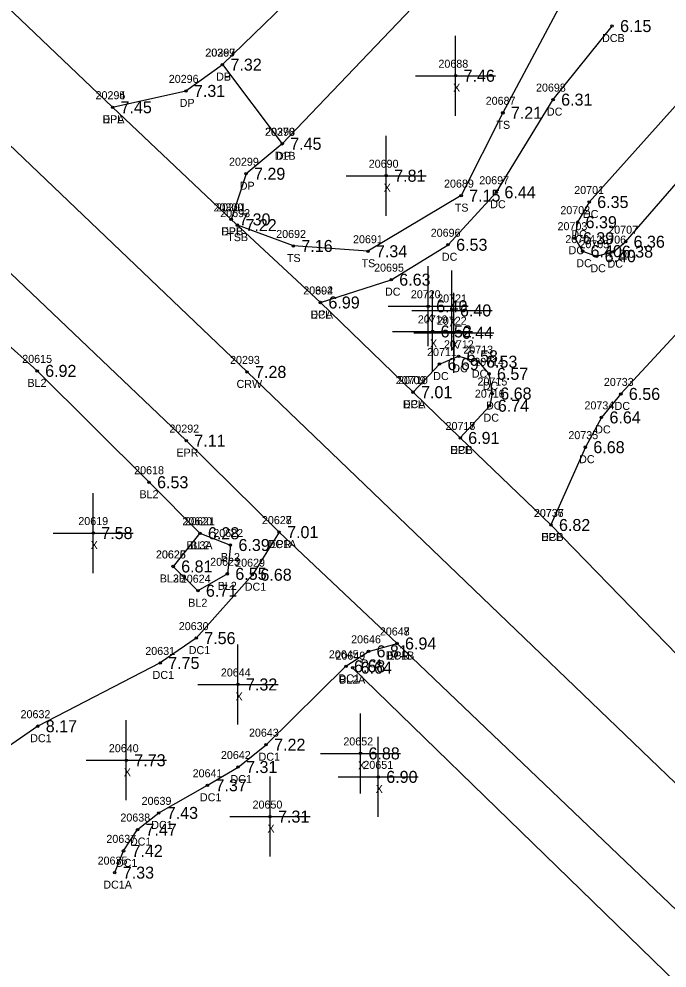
# Model space of a CAD drawing. Extents: x 2608745 to 2610333, y 641917 to 643463.
# Drawn here: x 2609150.7 to 2609231.6, y 642947.8 to 643066.4 of the extents above; entities that cross this region are included whole.
import ezdxf

# ---------------------------------------------------------------- set-up
doc = ezdxf.new("R2010")
doc.units = 0
for name, color, linetype in [('RD_DTM_BkLn1', 7, 'Continuous'), ('RD_DTM_BkLn2', 7, 'Continuous'), ('RD_DTM_BkLn_txCode', 7, 'Continuous'), ('RD_EX_Conc', 7, 'Continuous'), ('RD_EX_Conc_txCode', 7, 'Continuous'), ('RD_EX_Driveway', 7, 'Continuous'), ('RD_EX_Driveway_txCode', 7, 'Continuous'), ('RD_EX_Misc', 7, 'Continuous'), ('RD_EX_Misc_txCode', 7, 'Continuous'), ('RD_EX_Road', 7, 'Continuous'), ('RD_EX_Road_txCode', 7, 'Continuous'), ('RD_EX_TX_Conc_ELEV', 7, 'Continuous'), ('RD_EX_TX_Driveway_ELEV', 7, 'Continuous'), ('RD_EX_TX_Misc_ELEV', 7, 'Continuous'), ('RD_EX_TX_Road_ELEV', 7, 'Continuous'), ('RD_HC_Survey_ELEV', 7, 'Continuous'), ('RD_HC_Survey_txCode', 7, 'Continuous'), ('RD_SMD_Locator', 7, 'Continuous')]:
    doc.layers.add(name, color=color, linetype=linetype)

msp = doc.modelspace()

# ---------------------------------------------------------------- linework, layer by layer
at = {"layer": 'RD_DTM_BkLn1'}
msp.add_line((2609173.31, 643002.14), (2609169.97, 642997.99), dxfattribs=at)
for points in [[(2608814.73, 643373.65), (2608890.45, 643300.26), (2608962.19, 643231.31), (2609034.91, 643161.19), (2609108.48, 643089.9), (2609179.19, 643022.29), (2609255.71, 642948.78), (2609335.19, 642871.73), (2609410.7, 642798.48), (2609491.67, 642719.95), (2609518.07, 642695.15)], [(2609126.24, 643046.39), (2609152.99, 643022.42), (2609166.96, 643008.51), (2609173.31, 643002.14), (2609177.12, 643000.67), (2609176.73, 642997.07), (2609173.06, 642994.96), (2609169.97, 642997.99)], [(2609192.37, 642985.35), (2609243.37, 642935.72), (2609261.87, 642916.52), (2609260.59, 642912.35), (2609259.28, 642907.38), (2609258.26, 642905.81), (2609261.26, 642892.15), (2609237.69, 642882.51), (2609215.85, 642875.95), (2609203.21, 642875.18)]]:
    msp.add_lwpolyline(points, dxfattribs=at)
at = {"layer": 'RD_DTM_BkLn2'}
msp.add_lwpolyline([(2609237.48, 643094.02), (2609220.03, 643071.4), (2609211.12, 643054.65), (2609205.92, 643044.31), (2609194.28, 643037.36), (2609184.97, 643038.02), (2609177.99, 643040.62)], dxfattribs=at)
at = {"layer": 'RD_EX_Conc'}
for points in [[(2609188.35, 643030.96), (2609197.19, 643033.81), (2609204.29, 643038.17), (2609210.32, 643044.73), (2609217.4, 643056.3), (2609224.76, 643065.49)], [(2609270, 643061.09), (2609272.61, 643058.59), (2609260.56, 643044.7), (2609257.72, 643041.97), (2609255.04, 643040.51), (2609251.59, 643039.85), (2609247.63, 643039.74), (2609244.98, 643039.01), (2609242.03, 643037.04), (2609225.85, 643019.54), (2609223.43, 643016.61), (2609221.42, 643012.89), (2609217.13, 643003.17)], [(2609234.1, 643057.12), (2609221.9, 643043.51), (2609220.45, 643040.99), (2609220.11, 643038.99), (2609221.07, 643037.37), (2609222.83, 643036.74), (2609224.97, 643037.31), (2609226.44, 643038.55), (2609238.84, 643052.81)], [(2609199.91, 643019.76), (2609203.21, 643023.27), (2609205.6, 643024.24), (2609208.03, 643023.57), (2609209.39, 643022.05), (2609209.8, 643019.59), (2609209.49, 643018.07), (2609205.8, 643014.04)], [(2609183.19, 643002.28), (2609179.86, 642996.96), (2609172.85, 642989.04), (2609168.35, 642985.94), (2609153.06, 642978.04), (2609140.29, 642969.22), (2609118.23, 642952.79)], [(2609162.68, 642959.75), (2609163.77, 642962.47), (2609165.52, 642965.13), (2609168.17, 642967.21), (2609174.25, 642970.66), (2609178.07, 642972.94), (2609181.57, 642975.73), (2609191.54, 642985.52), (2609194.35, 642987.39), (2609197.91, 642988.37)]]:
    msp.add_lwpolyline(points, dxfattribs=at)
at = {"layer": 'RD_EX_Driveway'}
for points in [[(2609166.46, 643161.04), (2609160.17, 643148.26), (2609190.36, 643122.83), (2609213.32, 643102.87), (2609223.77, 643094.8), (2609208.75, 643077.17), (2609183.58, 643050.78)], [(2609100.57, 643145.92), (2609122.94, 643140.66), (2609155.04, 643137.1), (2609182.05, 643117.56), (2609202.04, 643097.35), (2609199.5, 643083.36), (2609176.12, 643060.67)], [(2609162.4, 643055.35), (2609171.56, 643057.39), (2609176.12, 643060.67), (2609183.58, 643050.78), (2609179.06, 643047.04), (2609177.21, 643041.34)]]:
    msp.add_lwpolyline(points, dxfattribs=at)
at = {"layer": 'RD_EX_Misc'}
for p, q in [((2609205.22, 643054.28), (2609205.22, 643064.28)), ((2609200.22, 643059.28), (2609210.22, 643059.28)), ((2609196.56, 643041.79), (2609196.56, 643051.79)), ((2609191.56, 643046.79), (2609201.56, 643046.79)), ((2609201.8, 643025.49), (2609201.8, 643035.49)), ((2609204.77, 643024.97), (2609204.77, 643034.97)), ((2609202.35, 643022.35), (2609202.35, 643032.35)), ((2609205, 643022.18), (2609205, 643032.18)), ((2609196.8, 643030.49), (2609206.8, 643030.49)), ((2609199.77, 643029.97), (2609209.77, 643029.97)), ((2609197.35, 643027.35), (2609207.35, 643027.35)), ((2609200, 643027.18), (2609210, 643027.18)), ((2609159.99, 642997.16), (2609159.99, 643007.16)), ((2609154.99, 643002.16), (2609164.99, 643002.16)), ((2609178.06, 642978.25), (2609178.06, 642988.25)), ((2609173.06, 642983.25), (2609183.06, 642983.25)), ((2609193.35, 642969.64), (2609193.35, 642979.64)), ((2609164.12, 642968.79), (2609164.12, 642978.79)), ((2609195.57, 642966.71), (2609195.57, 642976.71)), ((2609188.35, 642974.64), (2609198.35, 642974.64)), ((2609159.12, 642973.79), (2609169.12, 642973.79)), ((2609182.06, 642961.75), (2609182.06, 642971.75)), ((2609190.57, 642971.71), (2609200.57, 642971.71)), ((2609177.06, 642966.75), (2609187.06, 642966.75))]:
    msp.add_line(p, q, dxfattribs=at)
at = {"layer": 'RD_EX_Road'}
for points in [[(2608806.89, 643364.99), (2608810.18, 643361.1), (2608820.75, 643351.25), (2608881.81, 643292.24), (2608917.83, 643257.49), (2608933.21, 643242.71), (2608954.07, 643222.83), (2609026.06, 643154.19), (2609039.6, 643139.96), (2609073.88, 643106.95), (2609100.48, 643081.89), (2609124.19, 643058.87), (2609171.61, 643013.71), (2609183.19, 643002.28), (2609197.91, 642988.37), (2609247.59, 642940.95), (2609328.02, 642863.6), (2609402.61, 642790.3), (2609474.23, 642720.69), (2609483.84, 642711.58), (2609495.78, 642699.92), (2609509.81, 642686.45)], [(2609058.51, 643155.46), (2609096.06, 643119.37), (2609116.51, 643099.11), (2609162.4, 643055.35), (2609177.21, 643041.34), (2609188.35, 643030.96), (2609199.91, 643019.76), (2609205.8, 643014.04), (2609217.13, 643003.17), (2609235.83, 642983.9), (2609237.03, 642983.51), (2609256.8, 642965.04), (2609258.49, 642962.51), (2609263.65, 642957.66), (2609344.71, 642879.89), (2609418.83, 642806.19), (2609500.61, 642728.46), (2609512.38, 642716.82), (2609526.19, 642703.5)]]:
    msp.add_lwpolyline(points, dxfattribs=at)
at = {"layer": 'RD_SMD_Locator'}
for centre in [(2609224.76, 643065.49), (2609176.12, 643060.67), (2609176.12, 643060.67), (2609205.22, 643059.28), (2609171.56, 643057.39), (2609217.4, 643056.3), (2609162.4, 643055.35), (2609162.4, 643055.35), (2609211.12, 643054.65), (2609183.58, 643050.78), (2609183.58, 643050.78), (2609179.06, 643047.04), (2609196.56, 643046.79), (2609205.92, 643044.31), (2609210.32, 643044.73), (2609221.9, 643043.51), (2609177.21, 643041.34), (2609177.21, 643041.34), (2609177.99, 643040.62), (2609220.45, 643040.99), (2609184.97, 643038.02), (2609204.29, 643038.17), (2609220.11, 643038.99), (2609226.44, 643038.55), (2609194.28, 643037.36), (2609221.07, 643037.37), (2609224.97, 643037.31), (2609222.83, 643036.74), (2609197.19, 643033.81), (2609188.35, 643030.96), (2609188.35, 643030.96), (2609201.8, 643030.49), (2609204.77, 643029.97), (2609202.35, 643027.35), (2609205, 643027.18), (2609205.6, 643024.24), (2609203.21, 643023.27), (2609208.03, 643023.57), (2609152.99, 643022.42), (2609179.19, 643022.29), (2609209.39, 643022.05), (2609199.91, 643019.76), (2609199.91, 643019.76), (2609209.8, 643019.59), (2609225.85, 643019.54), (2609209.49, 643018.07), (2609223.43, 643016.61), (2609171.61, 643013.71), (2609205.8, 643014.04), (2609205.8, 643014.04), (2609221.42, 643012.89), (2609166.96, 643008.51), (2609217.13, 643003.17), (2609217.13, 643003.17), (2609159.99, 643002.16), (2609173.31, 643002.14), (2609173.31, 643002.14), (2609183.19, 643002.28), (2609183.19, 643002.28), (2609177.12, 643000.67), (2609169.97, 642997.99), (2609169.97, 642997.99), (2609176.73, 642997.07), (2609179.86, 642996.96), (2609173.06, 642994.96), (2609172.85, 642989.04), (2609197.91, 642988.37), (2609197.91, 642988.37), (2609194.35, 642987.39), (2609168.35, 642985.94), (2609191.54, 642985.52), (2609192.37, 642985.35), (2609178.06, 642983.25), (2609153.06, 642978.04), (2609181.57, 642975.73), (2609193.35, 642974.64), (2609164.12, 642973.79), (2609178.07, 642972.94), (2609195.57, 642971.71), (2609174.25, 642970.66), (2609168.17, 642967.21), (2609182.06, 642966.75), (2609165.52, 642965.13), (2609163.77, 642962.47), (2609162.68, 642959.75)]:
    msp.add_circle(centre, 0.15, dxfattribs=at)

# ---------------------------------------------------------------- texts
at = {"layer": 'RD_DTM_BkLn_txCode'}
for s, p in [('20687', (2609208.98, 643055.65)), ('TS', (2609210.32, 643052.65)), ('20689', (2609203.78, 643045.31)), ('TS', (2609205.12, 643042.31)), ('20693', (2609175.85, 643041.62)), ('TSB', (2609176.72, 643038.62)), ('20692', (2609182.83, 643039.02)), ('20691', (2609192.42, 643038.36)), ('TS', (2609184.17, 643036.02)), ('TS', (2609193.49, 643035.36)), ('20615', (2609151.13, 643023.42)), ('BL2', (2609151.78, 643020.42)), ('20618', (2609165.1, 643009.51)), ('BL2', (2609165.76, 643006.51)), ('20620', (2609171.12, 643003.14)), ('20621', (2609171.45, 643003.14)), ('20622', (2609174.98, 643001.67)), ('BL3A', (2609171.61, 643000.14)), ('BL2', (2609172.1, 643000.14)), ('20626', (2609167.81, 642998.99)), ('20625', (2609167.83, 642998.99)), ('20623', (2609174.59, 642998.07)), ('BL2', (2609175.92, 642998.67)), ('BL2B', (2609168.3, 642995.99)), ('BL3B', (2609168.3, 642995.99)), ('20624', (2609170.92, 642995.96)), ('BL2', (2609175.53, 642995.07)), ('BL2', (2609171.85, 642992.96)), ('20649', (2609190.23, 642986.35)), ('BL2A', (2609190.68, 642983.35))]:
    msp.add_text(s, height=1, dxfattribs=at).set_placement(p)
at = {"layer": 'RD_EX_Conc_txCode'}
for s, p in [('DCB', (2609223.51, 643063.49)), ('20698', (2609215.26, 643057.3)), ('DC', (2609216.62, 643054.3)), ('20697', (2609208.18, 643045.73)), ('20701', (2609220.03, 643044.51)), ('DC', (2609209.55, 643042.73)), ('20702', (2609218.3, 643041.99)), ('DC', (2609221.12, 643041.51)), ('20703', (2609217.95, 643039.99)), ('20707', (2609224.28, 643039.55)), ('20696', (2609202.12, 643039.17)), ('20704', (2609218.92, 643038.37)), ('DC', (2609219.67, 643038.99)), ('20706', (2609222.79, 643038.31)), ('20705', (2609220.68, 643037.74)), ('DC', (2609203.51, 643036.17)), ('DC', (2609219.33, 643036.99)), ('DC', (2609225.66, 643036.55)), ('20695', (2609195.05, 643034.81)), ('DC', (2609220.29, 643035.37)), ('DC', (2609222.05, 643034.74)), ('DC', (2609224.19, 643035.31)), ('20694', (2609186.21, 643031.96)), ('DC', (2609196.41, 643031.81)), ('DCA', (2609187.09, 643028.96)), ('20712', (2609203.77, 643025.24)), ('20711', (2609201.66, 643024.27)), ('20713', (2609206.19, 643024.57)), ('20714', (2609207.55, 643023.05)), ('DC', (2609204.82, 643022.24)), ('20710', (2609198.04, 643020.76)), ('DC', (2609202.43, 643021.27)), ('DC', (2609207.25, 643021.57)), ('20715', (2609207.96, 643020.59)), ('20733', (2609223.73, 643020.54)), ('DC', (2609208.61, 643020.05)), ('20716', (2609207.63, 643019.07)), ('DCA', (2609198.64, 643017.76)), ('DC', (2609209.02, 643017.59)), ('20734', (2609221.31, 643017.61)), ('DC', (2609225.07, 643017.54)), ('DC', (2609208.71, 643016.07)), ('20717', (2609203.97, 643015.04)), ('DC', (2609222.65, 643014.61)), ('20735', (2609219.3, 643013.89)), ('DCB', (2609204.55, 643012.04)), ('DC', (2609220.64, 643010.89)), ('20736', (2609214.99, 643004.17)), ('20628', (2609181.05, 643003.28)), ('DCB', (2609215.88, 643001.17)), ('DC1A', (2609181.76, 643000.28)), ('20629', (2609177.71, 642997.96)), ('DC1', (2609178.91, 642994.96)), ('20630', (2609170.67, 642990.04)), ('20647', (2609195.77, 642989.37)), ('20646', (2609192.18, 642988.39)), ('20631', (2609166.49, 642986.94)), ('DC1', (2609171.91, 642987.04)), ('20645', (2609189.4, 642986.52)), ('DC1B', (2609196.5, 642986.37)), ('DC1', (2609193.4, 642985.39)), ('DC1', (2609167.4, 642983.94)), ('DC1', (2609190.6, 642983.52)), ('20632', (2609150.92, 642979.04)), ('20643', (2609179.43, 642976.73)), ('DC1', (2609152.12, 642976.04)), ('20642', (2609175.93, 642973.94)), ('DC1', (2609180.63, 642973.73)), ('20641', (2609172.4, 642971.66)), ('DC1', (2609177.12, 642970.94)), ('DC1', (2609173.31, 642968.66)), ('20639', (2609166.03, 642968.21)), ('20638', (2609163.38, 642966.13)), ('DC1', (2609167.23, 642965.21)), ('20637', (2609161.63, 642963.47)), ('DC1', (2609164.58, 642963.13)), ('20635', (2609160.54, 642960.75)), ('DC1', (2609162.83, 642960.47)), ('DC1A', (2609161.25, 642957.75))]:
    msp.add_text(s, height=1, dxfattribs=at).set_placement(p)
at = {"layer": 'RD_EX_Driveway_txCode'}
for s, p in [('20369', (2609173.97, 643061.67)), ('20297', (2609174, 643061.67)), ('DP', (2609175.34, 643058.67)), ('DB', (2609175.34, 643058.67)), ('20296', (2609169.42, 643058.39)), ('20295', (2609160.28, 643056.35)), ('DP', (2609170.78, 643055.39)), ('DPA', (2609161.13, 643053.35)), ('20370', (2609181.42, 643051.78)), ('20298', (2609181.46, 643051.78)), ('20299', (2609176.94, 643048.04)), ('D1B', (2609182.64, 643048.78)), ('DP', (2609182.8, 643048.78)), ('DP', (2609178.28, 643045.04)), ('20300', (2609175.01, 643042.34)), ('DPB', (2609175.96, 643039.34))]:
    msp.add_text(s, height=1, dxfattribs=at).set_placement(p)
at = {"layer": 'RD_EX_Misc_txCode'}
for s, p in [('20688', (2609203.08, 643060.28)), ('X', (2609204.91, 643057.28)), ('20690', (2609194.38, 643047.79)), ('X', (2609196.25, 643044.79)), ('20720', (2609199.64, 643031.49)), ('20721', (2609202.93, 643030.97)), ('20719', (2609200.51, 643028.35)), ('X', (2609201.48, 643028.49)), ('20722', (2609202.89, 643028.18)), ('X', (2609204.45, 643027.97)), ('X', (2609202.03, 643025.35)), ('X', (2609204.69, 643025.18)), ('20619', (2609158.13, 643003.16)), ('X', (2609159.67, 643000.16)), ('20644', (2609175.92, 642984.25)), ('X', (2609177.75, 642981.25)), ('20652', (2609191.21, 642975.64)), ('20640', (2609161.94, 642974.79)), ('X', (2609193.04, 642972.64)), ('20651', (2609193.71, 642972.71)), ('X', (2609163.81, 642971.79)), ('X', (2609195.25, 642969.71)), ('20650', (2609179.88, 642967.75)), ('X', (2609181.74, 642964.75))]:
    msp.add_text(s, height=1, dxfattribs=at).set_placement(p)
at = {"layer": 'RD_EX_Road_txCode'}
for s, p in [('20294', (2609160.28, 643056.35)), ('EPL', (2609161.19, 643053.35)), ('20301', (2609175.33, 643042.34)), ('EPL', (2609176, 643039.34)), ('20302', (2609186.2, 643031.96)), ('EPL', (2609187.15, 643028.96)), ('20709', (2609197.75, 643020.76)), ('EPL', (2609198.71, 643017.76)), ('20292', (2609169.49, 643014.71)), ('20718', (2609203.97, 643015.04)), ('EPR', (2609170.38, 643011.71)), ('EPL', (2609204.6, 643012.04)), ('20737', (2609215.01, 643004.17)), ('20627', (2609181.05, 643003.28)), ('EPL', (2609215.93, 643001.17)), ('EPR', (2609181.97, 643000.28)), ('20648', (2609195.77, 642989.37)), ('EPR', (2609196.68, 642986.37))]:
    msp.add_text(s, height=1, dxfattribs=at).set_placement(p)
at = {"layer": 'RD_EX_TX_Conc_ELEV'}
for s, p in [('6.15', (2609225.76, 643064.74)), ('6.31', (2609218.4, 643055.55)), ('6.44', (2609211.32, 643043.98)), ('6.35', (2609222.9, 643042.76)), ('6.39', (2609221.45, 643040.24)), ('6.39', (2609221.11, 643038.24)), ('6.36', (2609227.44, 643037.8)), ('6.53', (2609205.29, 643037.42)), ('6.40', (2609222.07, 643036.62)), ('6.38', (2609225.97, 643036.56)), ('6.40', (2609223.83, 643035.99)), ('6.63', (2609198.19, 643033.06)), ('6.99', (2609189.35, 643030.21)), ('6.69', (2609204.21, 643022.52)), ('6.58', (2609206.6, 643023.49)), ('6.53', (2609209.03, 643022.82)), ('6.57', (2609210.39, 643021.3)), ('7.01', (2609200.91, 643019.01)), ('6.68', (2609210.8, 643018.84)), ('6.56', (2609226.85, 643018.79)), ('6.74', (2609210.49, 643017.32)), ('6.64', (2609224.43, 643015.86)), ('6.91', (2609206.8, 643013.29)), ('6.68', (2609222.42, 643012.14)), ('6.82', (2609218.13, 643002.42)), ('7.01', (2609184.19, 643001.53)), ('6.68', (2609180.86, 642996.21)), ('7.56', (2609173.85, 642988.29)), ('6.94', (2609198.91, 642987.62)), ('6.81', (2609195.35, 642986.64)), ('7.75', (2609169.35, 642985.19)), ('6.68', (2609192.54, 642984.77)), ('8.17', (2609154.06, 642977.29)), ('7.22', (2609182.57, 642974.98)), ('7.31', (2609179.07, 642972.19)), ('7.37', (2609175.25, 642969.91)), ('7.43', (2609169.17, 642966.46)), ('7.47', (2609166.52, 642964.38)), ('7.42', (2609164.77, 642961.72)), ('7.33', (2609163.68, 642959))]:
    msp.add_text(s, height=1.5, dxfattribs=at).set_placement(p)
at = {"layer": 'RD_EX_TX_Driveway_ELEV'}
for s, p in [('7.32', (2609177.12, 643059.92)), ('7.32', (2609177.12, 643059.92)), ('7.31', (2609172.56, 643056.64)), ('7.45', (2609163.4, 643054.6)), ('7.45', (2609184.58, 643050.03)), ('7.45', (2609184.58, 643050.03)), ('7.29', (2609180.06, 643046.29)), ('7.30', (2609178.21, 643040.59))]:
    msp.add_text(s, height=1.5, dxfattribs=at).set_placement(p)
at = {"layer": 'RD_EX_TX_Misc_ELEV'}
for s, p in [('7.46', (2609206.22, 643058.53)), ('7.21', (2609212.12, 643053.9)), ('7.81', (2609197.56, 643046.04)), ('7.15', (2609206.92, 643043.56)), ('7.22', (2609178.99, 643039.87)), ('7.16', (2609185.97, 643037.27)), ('7.34', (2609195.28, 643036.61)), ('6.40', (2609202.8, 643029.74)), ('6.40', (2609205.77, 643029.22)), ('6.52', (2609203.35, 643026.6)), ('6.44', (2609206, 643026.43)), ('6.92', (2609153.99, 643021.67)), ('6.53', (2609167.96, 643007.76)), ('7.58', (2609160.99, 643001.41)), ('6.28', (2609174.31, 643001.39)), ('6.28', (2609174.31, 643001.39)), ('6.39', (2609178.12, 642999.92)), ('6.81', (2609170.97, 642997.24)), ('6.81', (2609170.97, 642997.24)), ('6.55', (2609177.73, 642996.32)), ('6.71', (2609174.06, 642994.21)), ('6.64', (2609193.37, 642984.6)), ('7.32', (2609179.06, 642982.5)), ('6.88', (2609194.35, 642973.89)), ('7.73', (2609165.12, 642973.04)), ('6.90', (2609196.57, 642970.96)), ('7.31', (2609183.06, 642966))]:
    msp.add_text(s, height=1.5, dxfattribs=at).set_placement(p)
at = {"layer": 'RD_EX_TX_Road_ELEV'}
for s, p in [('7.45', (2609163.4, 643054.6)), ('7.30', (2609178.21, 643040.59)), ('6.99', (2609189.35, 643030.21)), ('7.01', (2609200.91, 643019.01)), ('7.11', (2609172.61, 643012.96)), ('6.91', (2609206.8, 643013.29)), ('6.82', (2609218.13, 643002.42)), ('7.01', (2609184.19, 643001.53)), ('6.94', (2609198.91, 642987.62))]:
    msp.add_text(s, height=1.5, dxfattribs=at).set_placement(p)
at = {"layer": 'RD_HC_Survey_ELEV'}
msp.add_text('7.28', height=1.5, dxfattribs=at).set_placement((2609180.19, 643021.54))
at = {"layer": 'RD_HC_Survey_txCode'}
for s, p in [('20293', (2609177.07, 643023.29)), ('CRW', (2609177.88, 643020.29))]:
    msp.add_text(s, height=1, dxfattribs=at).set_placement(p)

doc.saveas('drawing.dxf')
